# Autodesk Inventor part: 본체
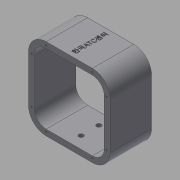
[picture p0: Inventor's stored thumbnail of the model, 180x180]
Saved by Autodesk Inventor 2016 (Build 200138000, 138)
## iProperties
Created: 2016-12
Part Number: 본체
Material: 일반
Document SubType Name: Modeling
Designer: mduedu
Density: 1 g/cm^3
Appearance: 기본값
Author: mduedu
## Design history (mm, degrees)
sketch "스케치1"
  geometry: L1 (-46, 42)-(-46, -36); L2 (-16, 72)-(62, 72); L3 (92, 42)-(92, -36); L4 (62, -66)-(-16, -66); A1 r 30 centre (-16, -36) between (-46, -36) and (-16, -66); A2 r 30 centre (62, 42) between (92, 42) and (62, 72); A3 r 30 centre (62, -36) between (62, -66) and (92, -36); A4 r 30 centre (-16, 42) between (-16, 72) and (-46, 42); 1 further point
  constraints: 8 end point, 8 point on circle, 8 tangent, 4 centre point, 3 equal radius, 1 horizontal, 1 perpendicular, 1 vertical
  dimensions: "d83" = 30 radius of A2; "d84" = 92 distance from line of L3 point (0, 0); "d85" = 138 distance between parallel lines of L4 L2; "d86" = 46 distance from line of L1 point (0, 0); "d87" = 72 distance from line of point (0, 0) L2
extrude "돌출1" new body sketch "스케치1" stored distance "d3" = 70; taper "d4" = 0 deg
feature "쉘1" dims "d5" = 10
sketch "스케치10"
  geometry: L1 (78, 70)-(0, 70) reference; L2 (-30, 70)-(-30, 0) reference; 4 further points
  constraints: 1 coincident, 1 horizontal alignment, 1 midpoint, 1 vertical alignment, 1 other
  dimensions: "d88" = 35 distance of point (39, 35) point (39, 70) (derived); "d89" = 69 distance from line of point (39, 35) L2 (derived)
feature "엠보싱1" sketch "스케치10" dims "d61" = 0.5, "d62" = 0, "d83" = 30, "d84" = 92, "d85" = 138, "d86" = 46, "d87" = 72
sketch "스케치11"
  geometry: L1 (-36, -36)-(-36, 42) reference; L2 (-16, 62)-(62, 62) reference; L3 (82, 42)-(82, -36) reference; L4 (62, -56)-(-16, -56) reference; L5 (-16, -66)-(62, -66) reference; L6 (92, -36)-(92, 42) reference; L7 (62, 72)-(-16, 72) reference; L8 (-46, 42)-(-46, -36) reference; L9 (-16, 66)-(62, 66); L10 (86, 42)-(86, -36); L11 (62, -60)-(-16, -60); L12 (-40, -36)-(-40, 42); A1 r 20 centre (-16, -36) between (-36, -36) and (-16, -56) reference; A2 r 20 centre (-16, 42) between (-16, 62) and (-36, 42) reference; A3 r 20 centre (62, 42) between (82, 42) and (62, 62) reference; A4 r 20 centre (62, -36) between (62, -56) and (82, -36) reference; A5 r 30 centre (-16, -36) between (-46, -36) and (-16, -66) reference; A6 r 30 centre (62, -36) between (62, -66) and (92, -36) reference; A7 r 30 centre (62, 42) between (92, 42) and (62, 72) reference; A8 r 30 centre (-16, 42) between (-16, 72) and (-46, 42) reference; A9 r 24 centre (62, 42) between (86, 42) and (62, 66); A10 r 24 centre (62, -36) between (62, -60) and (86, -36); A11 r 24 centre (-16, -36) between (-40, -36) and (-16, -60); A12 r 24 centre (-16, 42) between (-16, 66) and (-40, 42); 8 further points
  constraints: 8 coincident, 8 end point, 8 point on circle, 4 centre point, 7 other
  dimensions: "d90" = 6 distance between parallel lines of L9 L7
hole "구멍3" sketch "스케치11" at (-16, 66), (-40, 42), (-40, -36), (-16, -60), (62, -60), (86, -36), (86, 42), (62, 66) diameter "d63" = 3.242; stored, may be unused: countersink angle "d67" = 90 deg, drill point angle "d69" = 120 deg; dims "d64" = 8.6, "d65" = 4, "d66" = 2, "d68" = 10.6
sketch "스케치12"
  geometry: L1 (16, -56)-(-62, -56) reference; L2 (-82, -36)-(-82, 42) reference; L3 (-62, 62)-(16, 62) reference; L4 (36, 42)-(36, -36) reference; L5 (46, -36)-(46, 42) reference; L6 (16, 72)-(-62, 72) reference; L7 (-92, 42)-(-92, -36) reference; L8 (-62, -66)-(16, -66) reference; L9 (-62, 66)-(16, 66); L10 (40, 42)-(40, -36); L11 (16, -60)-(-62, -60); L12 (-86, -36)-(-86, 42); A1 r 20 centre (16, -36) between (16, -56) and (36, -36) reference; A2 r 20 centre (-62, -36) between (-82, -36) and (-62, -56) reference; A3 r 20 centre (-62, 42) between (-62, 62) and (-82, 42) reference; A4 r 20 centre (16, 42) between (36, 42) and (16, 62) reference; A5 r 30 centre (16, -36) between (16, -66) and (46, -36) reference; A6 r 30 centre (16, 42) between (46, 42) and (16, 72) reference; A7 r 30 centre (-62, 42) between (-62, 72) and (-92, 42) reference; A8 r 30 centre (-62, -36) between (-92, -36) and (-62, -66) reference; A9 r 24 centre (16, 42) between (40, 42) and (16, 66); A10 r 24 centre (16, -36) between (16, -60) and (40, -36); A11 r 24 centre (-62, -36) between (-86, -36) and (-62, -60); A12 r 24 centre (-62, 42) between (-62, 66) and (-86, 42); 8 further points
  constraints: 8 coincident, 8 end point, 8 point on circle, 4 centre point, 7 other
  dimensions: "d91" = 6 distance between parallel lines of L9 L6
hole "구멍5" sketch "스케치12" at (-62, 66), (-86, 42), (-86, -36), (-62, -60), (16, -60), (40, -36), (40, 42), (16, 66) diameter "d70" = 3.242; stored, may be unused: countersink angle "d74" = 90 deg, drill point angle "d76" = 120 deg; dims "d71" = 8.6, "d72" = 4, "d73" = 2, "d75" = 10.6
sketch "스케치15"
  geometry: L1 (135.6, -35)-(-57.6, -35) reference; L2 (78, 0)-(0, 0) reference; L3 (0, -70)-(78, -70) reference; L4 (39, 0)-(39, -70); C1 r 4 at (39, -20); C2 r 4 at (39, -50); 1 further point
  constraints: 2 centre point, 2 end point, 2 midpoint, 1 point on line, 1 symmetric about line, 1 other
  dimensions: "d92" = 8 diameter of C1; "d93" = 15 distance from line of C1.centre L1
extrude "돌출6" cut sketch "스케치15" stored distance "d94" = 10; taper "d95" = 0 deg
node "솔리드1"
node "투영된 루프3"
node "투영된 루프4"
